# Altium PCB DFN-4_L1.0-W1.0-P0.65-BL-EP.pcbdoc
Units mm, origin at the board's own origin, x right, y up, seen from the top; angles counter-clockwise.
Board outline 13.89 x 14.16 mm, 2 copper layers (Top Layer, Bottom Layer), stack 0 mm thick; 1 components, 0 nets, 5 pads, 0 vias.
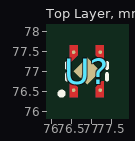
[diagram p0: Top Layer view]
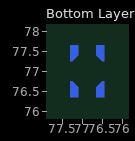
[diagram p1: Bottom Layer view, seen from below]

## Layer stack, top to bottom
Top Layer: signal copper (thickness not stored)
Bottom Layer: signal copper (thickness not stored)

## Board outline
83.739,69.85 69.85,69.85 69.85,84.008 83.739,84.008

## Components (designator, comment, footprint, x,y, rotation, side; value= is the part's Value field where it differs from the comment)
U? "" DFN-4_L1.0-W1.0-P0.65-BL-EP 76.885,77.007 r0 top

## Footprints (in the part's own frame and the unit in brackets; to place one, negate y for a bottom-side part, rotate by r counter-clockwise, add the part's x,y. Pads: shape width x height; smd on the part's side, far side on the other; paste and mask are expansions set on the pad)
DFN-4_L1.0-W1.0-P0.65-BL-EP [mm]
  round 0.092 smd: 1(-0.333,-0.475) 2(0.333,-0.474) 3(0.333,0.475) 4(-0.333,0.475)
  rect 0.48x0.48 smd rot 45: 5(0.004,0.001)
  Top Layer region: 0.425,-0.649 0.225,-0.649 0.225,-0.399 0.225,-0.399 0.375,-0.249 0.425,-0.249
  Top Layer region: -0.225,-0.4 -0.225,-0.65 -0.425,-0.65 -0.425,-0.25 -0.375,-0.25
  Top Layer region: -0.425,0.651 -0.225,0.651 -0.225,0.401 -0.225,0.401 -0.375,0.251 -0.425,0.251
  Top Layer region: 0.425,0.651 0.225,0.651 0.225,0.401 0.225,0.401 0.375,0.251 0.425,0.251
  Bottom Layer region: 0.425,-0.649 0.225,-0.649 0.225,-0.399 0.225,-0.399 0.375,-0.249 0.425,-0.249
  Bottom Layer region: -0.225,-0.4 -0.225,-0.65 -0.425,-0.65 -0.425,-0.25 -0.375,-0.25
  Bottom Layer region: -0.425,0.651 -0.225,0.651 -0.225,0.401 -0.225,0.401 -0.375,0.251 -0.425,0.251
  Bottom Layer region: 0.425,0.651 0.225,0.651 0.225,0.401 0.225,0.401 0.375,0.251 0.425,0.251
  Multi-Layer region: 0.425,-0.649 0.225,-0.649 0.225,-0.399 0.225,-0.399 0.375,-0.249 0.425,-0.249
  Multi-Layer region: -0.225,-0.4 -0.225,-0.65 -0.425,-0.65 -0.425,-0.25 -0.375,-0.25
  Multi-Layer region: -0.425,0.651 -0.225,0.651 -0.225,0.401 -0.225,0.401 -0.375,0.251 -0.425,0.251
  Multi-Layer region: 0.425,0.651 0.225,0.651 0.225,0.401 0.225,0.401 0.375,0.251 0.425,0.251
  silkscreen extent -0.68,-0.61 0.5,0.21

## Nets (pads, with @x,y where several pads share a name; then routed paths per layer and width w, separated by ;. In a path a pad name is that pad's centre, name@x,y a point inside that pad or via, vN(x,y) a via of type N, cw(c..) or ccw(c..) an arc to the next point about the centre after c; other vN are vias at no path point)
pads on no net: U?.1 U?.2 U?.3 U?.4 U?.5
